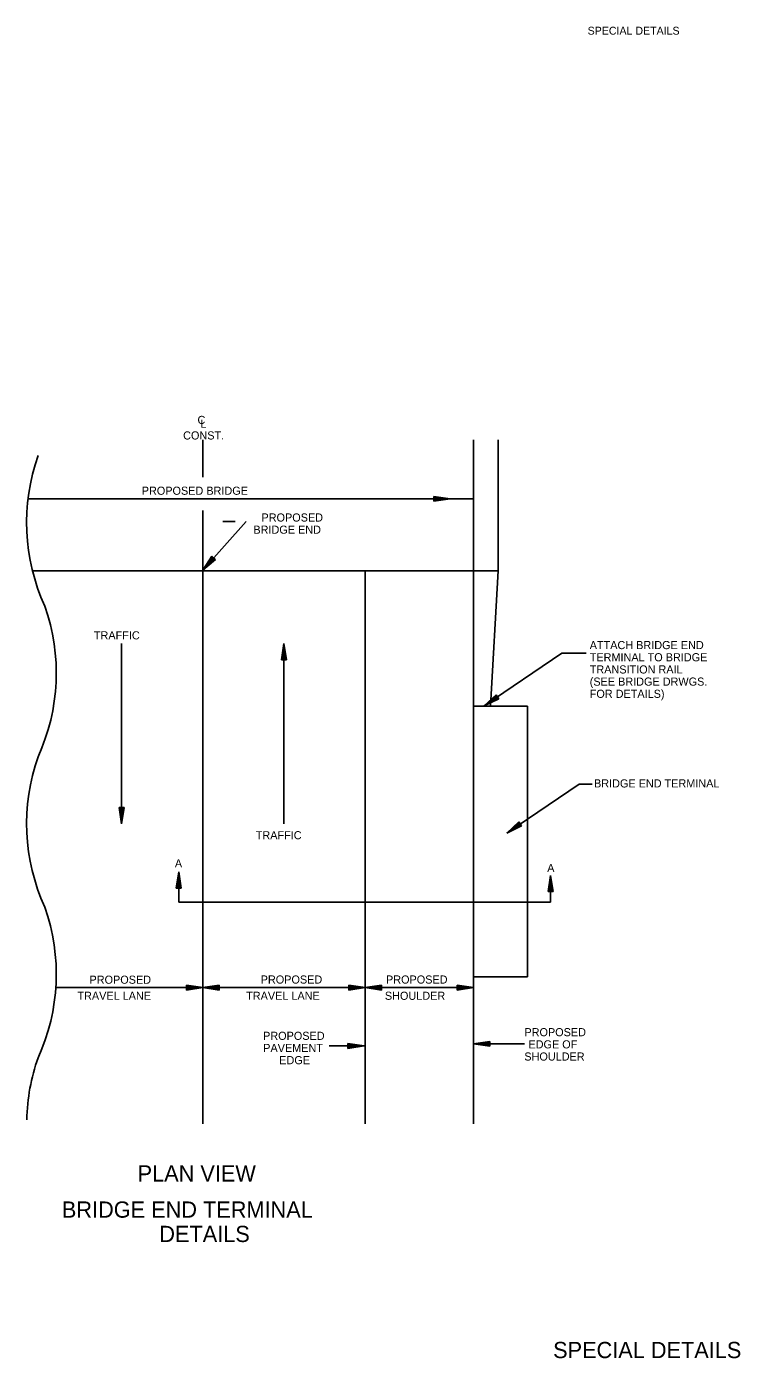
# Model space of a CAD drawing. Extents: x 1926836 to 1933254, y 596317 to 604524.
# Drawn here: x 1929352 to 1929879, y 601846 to 602831 of the extents above; entities that cross this region are included whole.
import ezdxf

# ---------------------------------------------------------------- set-up
doc = ezdxf.new("R2010")
doc.units = 0
for name, color, linetype in [('Default', 7, 'Continuous'), ('R_Annotation', 7, 'Continuous'), ('R_Border', 7, 'Continuous')]:
    doc.layers.add(name, color=color, linetype=linetype)

msp = doc.modelspace()

# ---------------------------------------------------------------- linework, layer by layer
at = {"layer": 'Default'}
for p, q in [((1929481.77, 602525.32), (1929481.77, 602497.71)), ((1929681.77, 602525.32), (1929681.77, 602428.52)), ((1929700.1, 602525.32), (1929700.1, 602428.52)), ((1929352.6, 602481.75), (1929681.77, 602481.75)), ((1929652.53, 602483.55), (1929664.53, 602481.75)), ((1929652.53, 602483.55), (1929652.53, 602479.95)), ((1929652.53, 602483.25), (1929662.53, 602481.75)), ((1929652.53, 602482.94), (1929660.46, 602481.75)), ((1929652.53, 602482.64), (1929658.46, 602481.75)), ((1929652.53, 602482.33), (1929656.43, 602481.75)), ((1929652.53, 602482.03), (1929654.43, 602481.75)), ((1929652.53, 602479.95), (1929664.53, 602481.75)), ((1929652.53, 602481.16), (1929656.43, 602481.75)), ((1929652.53, 602480.56), (1929660.46, 602481.75)), ((1929652.53, 602480.25), (1929662.53, 602481.75)), ((1929652.53, 602480.86), (1929658.46, 602481.75)), ((1929652.53, 602481.47), (1929654.43, 602481.75)), ((1929481.77, 602473.16), (1929481.77, 602019.77)), ((1929481.89, 602429.09), (1929513.77, 602464.87)), ((1929496.53, 602464.87), (1929505.57, 602464.89)), ((1929488.53, 602439.25), (1929481.89, 602429.09)), ((1929488.75, 602439.05), (1929483.22, 602430.59)), ((1929488.98, 602438.84), (1929484.6, 602432.13)), ((1929489.21, 602438.64), (1929485.93, 602433.62)), ((1929489.43, 602438.44), (1929487.28, 602435.14)), ((1929491.22, 602436.85), (1929488.53, 602439.25)), ((1929489.66, 602438.24), (1929488.61, 602436.63)), ((1929490.08, 602437.86), (1929488.61, 602436.63)), ((1929355.91, 602428.52), (1929700.1, 602428.52)), ((1929491.22, 602436.85), (1929481.89, 602429.09)), ((1929490.99, 602437.05), (1929483.22, 602430.59)), ((1929490.76, 602437.26), (1929484.6, 602432.13)), ((1929490.54, 602437.45), (1929485.93, 602433.62)), ((1929490.31, 602437.66), (1929487.28, 602435.14)), ((1929601.77, 602428.52), (1929601.77, 602019.77)), ((1929681.77, 602428.52), (1929681.77, 602328.52)), ((1929694.27, 602328.52), (1929700.1, 602428.52)), ((1929421.77, 602374.7), (1929421.77, 602241.59)), ((1929539.97, 602362.7), (1929541.77, 602374.7)), ((1929540.27, 602362.7), (1929541.77, 602372.7)), ((1929540.58, 602362.7), (1929541.77, 602370.63)), ((1929541.77, 602374.7), (1929541.77, 602241.59)), ((1929543.57, 602362.7), (1929541.77, 602374.7)), ((1929543.27, 602362.7), (1929541.77, 602372.7)), ((1929542.96, 602362.7), (1929541.77, 602370.63)), ((1929539.97, 602362.7), (1929543.57, 602362.7)), ((1929540.88, 602362.7), (1929541.77, 602368.63)), ((1929541.19, 602362.7), (1929541.77, 602366.6)), ((1929541.49, 602362.7), (1929541.77, 602364.6)), ((1929542.66, 602362.7), (1929541.77, 602368.63)), ((1929542.36, 602362.7), (1929541.77, 602366.6)), ((1929542.05, 602362.7), (1929541.77, 602364.6)), ((1929689.59, 602328.64), (1929747.1, 602367.63)), ((1929747.1, 602367.63), (1929765.19, 602367.63)), ((1929681.77, 602330.69), (1929681.77, 602019.77)), ((1929698.51, 602336.86), (1929689.59, 602328.64)), ((1929700.53, 602333.88), (1929689.59, 602328.64)), ((1929698.68, 602336.62), (1929691.25, 602329.76)), ((1929700.36, 602334.13), (1929691.25, 602329.76)), ((1929698.85, 602336.36), (1929692.96, 602330.92)), ((1929700.19, 602334.39), (1929692.96, 602330.92)), ((1929699.02, 602336.11), (1929694.61, 602332.04)), ((1929700.02, 602334.63), (1929694.61, 602332.04)), ((1929699.19, 602335.86), (1929696.29, 602333.19)), ((1929699.85, 602334.89), (1929696.29, 602333.19)), ((1929699.36, 602335.61), (1929697.95, 602334.31)), ((1929699.68, 602335.14), (1929697.95, 602334.31)), ((1929700.53, 602333.88), (1929698.51, 602336.86)), ((1929681.74, 602328.52), (1929681.74, 602128.52)), ((1929681.77, 602328.52), (1929721.81, 602328.52)), ((1929721.81, 602328.52), (1929721.81, 602128.52)), ((1929706.42, 602234.68), (1929760.03, 602270.87)), ((1929760.03, 602270.87), (1929769.49, 602270.94)), ((1929419.97, 602253.59), (1929421.77, 602241.59)), ((1929423.57, 602253.59), (1929419.97, 602253.59)), ((1929420.27, 602253.59), (1929421.77, 602243.59)), ((1929420.58, 602253.59), (1929421.77, 602245.66)), ((1929420.88, 602253.59), (1929421.77, 602247.66)), ((1929421.18, 602253.59), (1929421.77, 602249.69)), ((1929421.49, 602253.59), (1929421.77, 602251.69)), ((1929423.57, 602253.59), (1929421.77, 602241.59)), ((1929422.35, 602253.59), (1929421.77, 602249.69)), ((1929422.96, 602253.59), (1929421.77, 602245.66)), ((1929423.27, 602253.59), (1929421.77, 602243.59)), ((1929422.66, 602253.59), (1929421.77, 602247.66)), ((1929422.05, 602253.59), (1929421.77, 602251.69)), ((1929715.36, 602242.89), (1929706.42, 602234.68)), ((1929715.53, 602242.64), (1929708.08, 602235.8)), ((1929715.7, 602242.38), (1929709.79, 602236.96)), ((1929715.87, 602242.14), (1929711.45, 602238.07)), ((1929716.04, 602241.88), (1929713.13, 602239.21)), ((1929716.69, 602240.91), (1929713.13, 602239.21)), ((1929716.21, 602241.63), (1929714.79, 602240.33)), ((1929716.52, 602241.16), (1929714.79, 602240.33)), ((1929717.37, 602239.9), (1929715.36, 602242.89)), ((1929717.37, 602239.9), (1929706.42, 602234.68)), ((1929717.21, 602240.15), (1929708.08, 602235.8)), ((1929717.03, 602240.4), (1929709.79, 602236.96)), ((1929716.87, 602240.65), (1929711.45, 602238.07)), ((1929462.18, 602193.9), (1929463.98, 602205.9)), ((1929462.48, 602193.9), (1929463.98, 602203.9)), ((1929462.79, 602193.9), (1929463.98, 602201.83)), ((1929463.98, 602183.64), (1929463.98, 602205.9)), ((1929465.78, 602193.9), (1929463.98, 602205.9)), ((1929465.48, 602193.9), (1929463.98, 602203.9)), ((1929465.17, 602193.9), (1929463.98, 602201.83)), ((1929737.03, 602191.36), (1929738.83, 602203.36)), ((1929738.83, 602183.64), (1929738.83, 602203.36)), ((1929740.63, 602191.36), (1929738.83, 602203.36)), ((1929462.18, 602193.9), (1929465.78, 602193.9)), ((1929463.09, 602193.9), (1929463.98, 602199.83)), ((1929463.4, 602193.9), (1929463.98, 602197.8)), ((1929463.7, 602193.9), (1929463.98, 602195.8)), ((1929464.87, 602193.9), (1929463.98, 602199.83)), ((1929464.57, 602193.9), (1929463.98, 602197.8)), ((1929464.26, 602193.9), (1929463.98, 602195.8)), ((1929737.33, 602191.36), (1929738.83, 602201.36)), ((1929737.64, 602191.36), (1929738.83, 602199.29)), ((1929737.94, 602191.36), (1929738.83, 602197.29)), ((1929738.25, 602191.36), (1929738.83, 602195.26)), ((1929738.55, 602191.36), (1929738.83, 602193.26)), ((1929740.33, 602191.36), (1929738.83, 602201.36)), ((1929740.02, 602191.36), (1929738.83, 602199.29)), ((1929739.72, 602191.36), (1929738.83, 602197.29)), ((1929739.42, 602191.36), (1929738.83, 602195.26)), ((1929739.11, 602191.36), (1929738.83, 602193.26)), ((1929463.98, 602183.64), (1929738.83, 602183.64)), ((1929737.03, 602191.36), (1929740.63, 602191.36)), ((1929681.77, 602128.52), (1929721.81, 602128.52)), ((1929373.14, 602120.41), (1929481.77, 602120.41)), ((1929469.77, 602122.21), (1929481.77, 602120.41)), ((1929469.77, 602122.21), (1929469.77, 602118.61)), ((1929469.77, 602121.91), (1929479.77, 602120.41)), ((1929469.77, 602121.6), (1929477.7, 602120.41)), ((1929469.77, 602121.3), (1929475.7, 602120.41)), ((1929469.77, 602120.99), (1929473.67, 602120.41)), ((1929469.77, 602120.69), (1929471.67, 602120.41)), ((1929469.77, 602118.61), (1929481.77, 602120.41)), ((1929469.77, 602119.82), (1929473.67, 602120.41)), ((1929469.77, 602119.22), (1929477.7, 602120.41)), ((1929469.77, 602118.91), (1929479.77, 602120.41)), ((1929469.77, 602119.52), (1929475.7, 602120.41)), ((1929469.77, 602120.13), (1929471.67, 602120.41)), ((1929493.77, 602122.21), (1929481.77, 602120.41)), ((1929493.77, 602118.61), (1929481.77, 602120.41)), ((1929481.77, 602120.41), (1929601.77, 602120.41)), ((1929493.77, 602121.91), (1929483.77, 602120.41)), ((1929493.77, 602118.91), (1929483.77, 602120.41)), ((1929493.77, 602121.6), (1929485.84, 602120.41)), ((1929493.77, 602119.22), (1929485.84, 602120.41)), ((1929493.77, 602121.3), (1929487.84, 602120.41)), ((1929493.77, 602119.52), (1929487.84, 602120.41)), ((1929493.77, 602121), (1929489.87, 602120.41)), ((1929493.77, 602119.83), (1929489.87, 602120.41)), ((1929493.77, 602120.69), (1929491.87, 602120.41)), ((1929493.77, 602120.13), (1929491.87, 602120.41)), ((1929493.77, 602118.61), (1929493.77, 602122.21)), ((1929589.77, 602122.21), (1929601.77, 602120.41)), ((1929589.77, 602122.21), (1929589.77, 602118.61)), ((1929589.77, 602121.91), (1929599.77, 602120.41)), ((1929589.77, 602121.6), (1929597.7, 602120.41)), ((1929589.77, 602121.3), (1929595.7, 602120.41)), ((1929589.77, 602120.99), (1929593.67, 602120.41)), ((1929589.77, 602120.69), (1929591.67, 602120.41)), ((1929589.77, 602118.61), (1929601.77, 602120.41)), ((1929589.77, 602119.82), (1929593.67, 602120.41)), ((1929589.77, 602119.22), (1929597.7, 602120.41)), ((1929589.77, 602118.91), (1929599.77, 602120.41)), ((1929589.77, 602119.52), (1929595.7, 602120.41)), ((1929589.77, 602120.13), (1929591.67, 602120.41)), ((1929613.77, 602122.21), (1929601.77, 602120.41)), ((1929601.77, 602120.41), (1929681.77, 602120.41)), ((1929613.77, 602118.61), (1929601.77, 602120.41)), ((1929613.77, 602121.91), (1929603.77, 602120.41)), ((1929613.77, 602118.91), (1929603.77, 602120.41)), ((1929613.77, 602121.6), (1929605.84, 602120.41)), ((1929613.77, 602119.22), (1929605.84, 602120.41)), ((1929613.77, 602121.3), (1929607.84, 602120.41)), ((1929613.77, 602119.52), (1929607.84, 602120.41)), ((1929613.77, 602121), (1929609.87, 602120.41)), ((1929613.77, 602119.83), (1929609.87, 602120.41)), ((1929613.77, 602120.69), (1929611.87, 602120.41)), ((1929613.77, 602120.13), (1929611.87, 602120.41)), ((1929613.77, 602118.61), (1929613.77, 602122.21)), ((1929669.77, 602122.21), (1929681.77, 602120.41)), ((1929669.77, 602122.21), (1929669.77, 602118.61)), ((1929669.77, 602121.91), (1929679.77, 602120.41)), ((1929669.77, 602121.6), (1929677.7, 602120.41)), ((1929669.77, 602121.3), (1929675.7, 602120.41)), ((1929669.77, 602120.99), (1929673.67, 602120.41)), ((1929669.77, 602120.69), (1929671.67, 602120.41)), ((1929669.77, 602118.61), (1929681.77, 602120.41)), ((1929669.77, 602119.82), (1929673.67, 602120.41)), ((1929669.77, 602119.22), (1929677.7, 602120.41)), ((1929669.77, 602118.91), (1929679.77, 602120.41)), ((1929669.77, 602119.52), (1929675.7, 602120.41)), ((1929669.77, 602120.13), (1929671.67, 602120.41)), ((1929575.21, 602077.29), (1929601.06, 602077.29)), ((1929589.06, 602079.09), (1929601.06, 602077.29)), ((1929589.06, 602079.09), (1929589.06, 602075.49)), ((1929589.06, 602078.79), (1929599.06, 602077.29)), ((1929589.06, 602078.48), (1929596.99, 602077.29)), ((1929589.06, 602078.18), (1929594.99, 602077.29)), ((1929589.06, 602077.87), (1929592.96, 602077.29)), ((1929589.06, 602077.57), (1929590.96, 602077.29)), ((1929589.06, 602075.49), (1929601.06, 602077.29)), ((1929589.06, 602076.7), (1929592.96, 602077.29)), ((1929589.06, 602076.1), (1929596.99, 602077.29)), ((1929589.06, 602075.79), (1929599.06, 602077.29)), ((1929589.06, 602076.4), (1929594.99, 602077.29)), ((1929589.06, 602077.01), (1929590.96, 602077.29)), ((1929693.77, 602080.68), (1929681.77, 602078.88)), ((1929719.63, 602078.88), (1929681.77, 602078.88)), ((1929693.77, 602077.08), (1929681.77, 602078.88)), ((1929693.77, 602080.38), (1929683.77, 602078.88)), ((1929693.77, 602077.38), (1929683.77, 602078.88)), ((1929693.77, 602080.07), (1929685.84, 602078.88)), ((1929693.77, 602077.69), (1929685.84, 602078.88)), ((1929693.77, 602079.77), (1929687.84, 602078.88)), ((1929693.77, 602077.99), (1929687.84, 602078.88)), ((1929693.77, 602079.47), (1929689.87, 602078.88)), ((1929693.77, 602078.3), (1929689.87, 602078.88)), ((1929693.77, 602079.16), (1929691.87, 602078.88)), ((1929693.77, 602078.6), (1929691.87, 602078.88)), ((1929693.77, 602077.08), (1929693.77, 602080.68))]:
    msp.add_line(p, q, dxfattribs=at)
for centre, start, end in [((1929500.41, 602464.21), 160.57465, 204.52912), ((1929224.64, 602352.92), 335.47088, 19.42535), ((1929500.41, 602241.63), 160.57465, 204.52912), ((1929224.64, 602130.34), 335.47088, 19.42535), ((1929500.41, 602019.05), 160.57465, 178.55672)]:
    msp.add_arc(centre, 148.84, start, end, dxfattribs=at)

# ---------------------------------------------------------------- texts
for s, height, p in [('C', 6, (1929477.85, 602537.06)), ('L', 6, (1929479.96, 602534.24)), ('CONST.', 6, (1929467.22, 602525.61)), ('PROPOSED BRIDGE', 6, (1929436.65, 602484.75)), ('PROPOSED', 6, (1929525.14, 602464.95)), ('BRIDGE END', 6, (1929519.14, 602455.95)), ('TRAFFIC', 6, (1929401.27, 602377.84)), ('ATTACH BRIDGE END', 6, (1929767.72, 602370.64)), ('TERMINAL TO BRIDGE', 6, (1929767.72, 602361.64)), ('TRANSITION RAIL', 6, (1929767.72, 602352.64)), ('(SEE BRIDGE DRWGS.', 6, (1929767.72, 602343.64)), ('FOR DETAILS)', 6, (1929767.72, 602334.64)), ('BRIDGE END TERMINAL', 6, (1929770.88, 602268.39)), ('TRAFFIC', 6, (1929520.91, 602230.08)), ('A', 6, (1929461.12, 602209.28)), ('A', 6, (1929736.31, 602205.88)), ('PROPOSED', 6, (1929398.03, 602123.29)), ('PROPOSED', 6, (1929524.55, 602123.41)), ('PROPOSED', 6, (1929617.15, 602123.41)), ('TRAVEL LANE', 6, (1929389.11, 602111.41)), ('TRAVEL LANE', 6, (1929513.8, 602111.41)), ('SHOULDER', 6, (1929616.33, 602111.41)), ('PROPOSED', 6, (1929526.31, 602081.81)), ('PROPOSED', 6, (1929719.45, 602084.49)), ('PAVEMENT', 6, (1929526.42, 602072.81)), ('EDGE OF', 6, (1929722.42, 602075.49)), ('EDGE', 6, (1929538.26, 602063.81)), ('SHOULDER', 6, (1929719.38, 602066.49)), ('PLAN VIEW', 12, (1929433.59, 601977.1)), ('BRIDGE END TERMINAL', 12, (1929377.61, 601950.36)), ('DETAILS', 12, (1929449.61, 601932.36))]:
    msp.add_text(s, height=height, rotation=360, dxfattribs=at).set_placement(p)
at = {"layer": 'R_Annotation'}
msp.add_text('SPECIAL DETAILS', height=12, rotation=360, dxfattribs=at).set_placement((1929740.65, 601846.54))
at = {"layer": 'R_Border'}
msp.add_text('SPECIAL DETAILS', height=5.862, rotation=360, dxfattribs=at).set_placement((1929766.17, 602824.86))

doc.saveas('drawing.dxf')
